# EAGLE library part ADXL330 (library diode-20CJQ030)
Analog Devices ADXL330 Small, Low Power, 3-Axis ±3 g i MEMS Accelerometer Description: The ADXL330 is a small, thin, low power, complete three axis accelerometer with signal conditioned voltage outputs, all on a single monolithic IC. The product measures acceleration with a minimum full-scale range of ±3 g. It can measure the static acceleration of gravity in tilt-sensing applications, as well as dynamic acceleration resulting from motion, shock, or vibration. The user selects the bandwidth of the accelerometer using the CX, CY, and CZ capacitors at the XOUT, YOUT, and ZOUT pins. Bandwidths can be selected to suit the application, with a range of 0.5 Hz to 1,600 Hz for X and Y axes, and a range of 0.5 Hz to 550 Hz for the Z axis. The ADXL330 is available in a small, low-profile, 4 mm × 4 mm × 1.45 mm, 16-lead, plastic lead frame chip scale package (LFCSP_LQ). Features: 3-axis sensing Small, low-profile package - 4 mm × 4 mm × 1.45 mm LFCSP Low power - 200 ?A at VS = 2.0 V (typical) Single-supply operation - 2.0 V to 3.6 V 10,000 g shock survival Excellent temperature stability BW adjustment with a single capacitor per axis RoHS/WEEE lead-free compliant Applications: Cost-sensitive, low power, motion- and tilt-sensing applications - Mobile devices - Gaming systems - Disk drive protection - Image stabilization - Sports and health devices Please send any comments to: messi@users.sourceforge.net
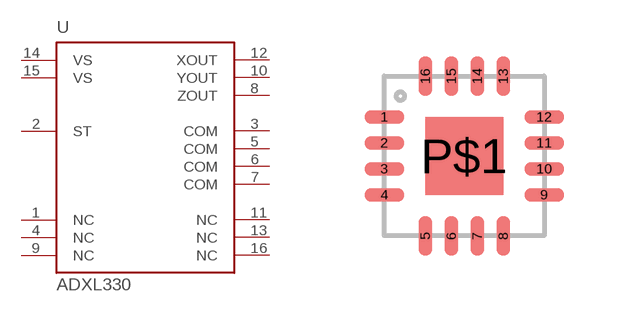
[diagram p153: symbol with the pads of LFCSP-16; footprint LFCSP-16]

Designator prefix U

## ADXL330  [LFCSP-16]
1  NC  nc
2  ST  in
3  COM  pwr
4  NC  nc
5  COM  pwr
6  COM  pwr
7  COM  pwr
8  ZOUT  out
9  NC  nc
10  YOUT  out
11  NC  nc
12  XOUT  out
13  NC  nc
14  VS  pwr
15  VS  pwr
16  NC  nc

## Footprint LFCSP-16 (pad centres in mm)
LFCSP-16 package for ADXL330 from Analog Devices
smd 1 x 0.35: 1 -2,0.975; 2 -2,0.325; 3 -2,-0.325; 4 -2,-0.975; 9 2,-0.975; 10 2,-0.325; 11 2,0.325; 12 2,0.975
smd 0.35 x 1: 5 -0.975,-2; 6 -0.325,-2; 7 0.325,-2; 8 0.975,-2; 13 0.975,2; 14 0.325,2; 15 -0.325,2; 16 -0.975,2
smd 1.95 x 1.95: P$1 0,0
